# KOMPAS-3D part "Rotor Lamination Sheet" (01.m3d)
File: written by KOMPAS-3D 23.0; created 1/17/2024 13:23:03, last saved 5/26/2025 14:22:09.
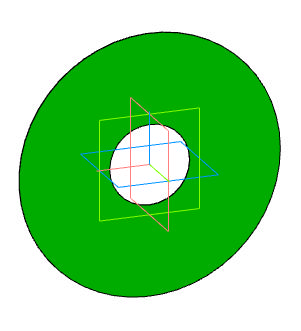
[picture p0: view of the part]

Document properties: Full file name: C:\WORK\KOMPAS\WiredWhite\Creating a Rotor Structure with an uneven air gap\Files\Rotor Lamination Sheet.m3d

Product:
- Part/product: Rotor Lamination Sheet
    Mass: 0.028588

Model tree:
1. Sketch:1
2. Lamination sheet
     Distance 1 = 0.3

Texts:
  Rotor inner diameter
  Rotor minimum diameter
